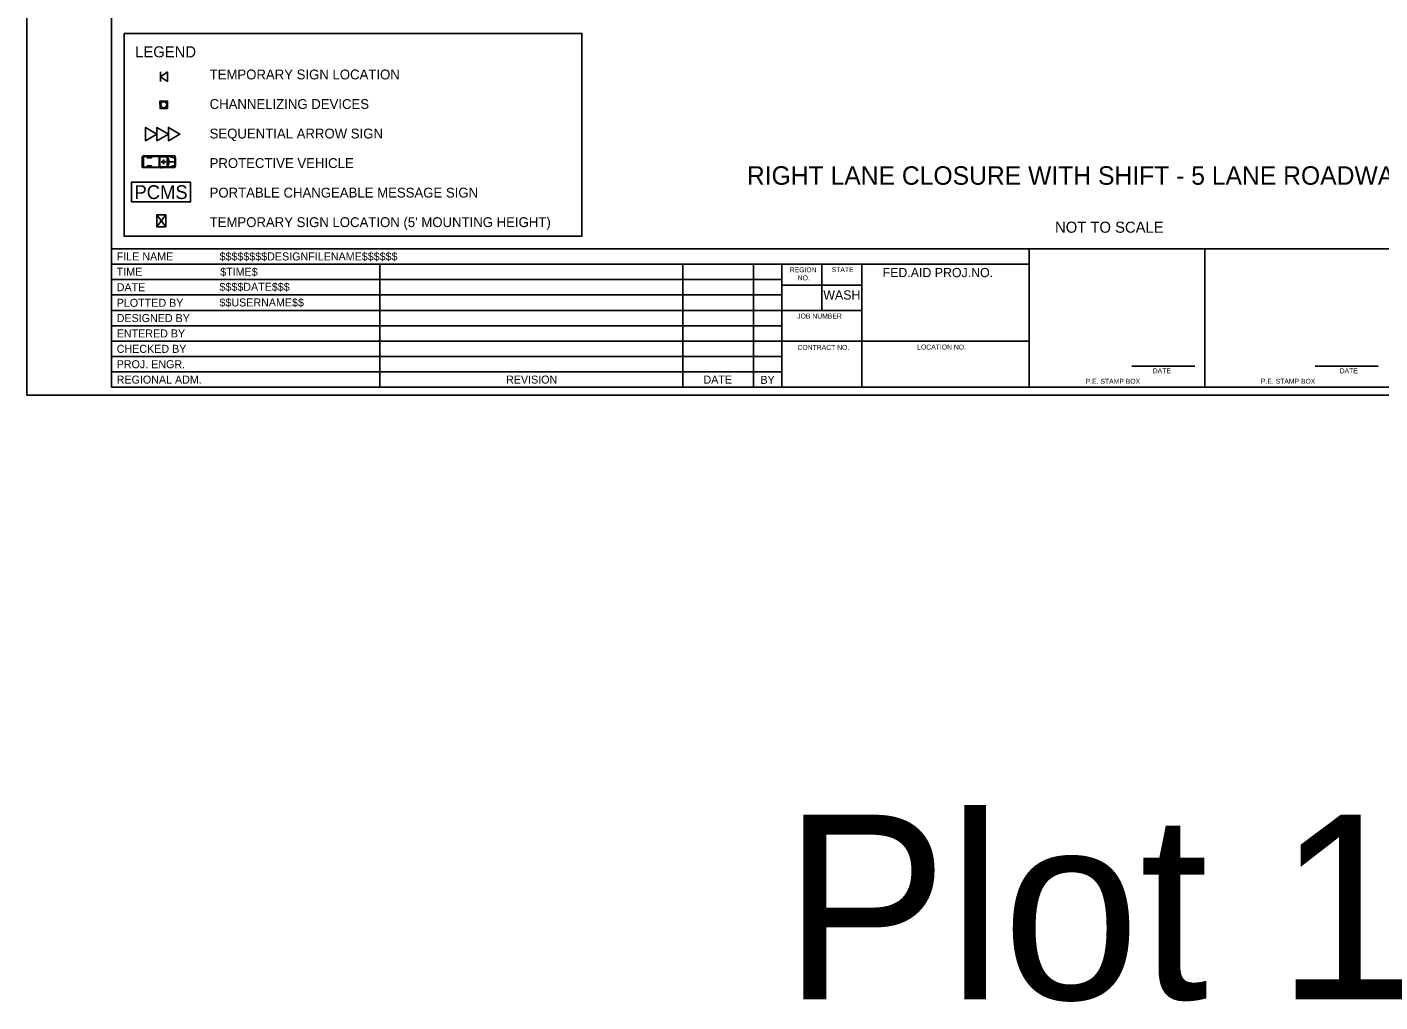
# Model space of a CAD drawing. Extents: x 99988 to 100172, y 99995 to 100047.
# Drawn here: x 99999.31 to 100010.31, y 99995.01 to 100002.93 of the extents above; entities that cross this region are included whole.
import ezdxf

# ---------------------------------------------------------------- set-up
doc = ezdxf.new("R2010")
doc.units = 0
for name, color, linetype in [('Default', 7, 'Continuous'), ('SH_DE_DetailBody1Text', 7, 'Continuous'), ('SH_DE_DetailHeading1Text', 7, 'Continuous'), ('SH_DE_DetailHeading2Text', 7, 'Continuous'), ('SH_DE_DetailHeading3Text', 7, 'Continuous'), ('SH_GI_PlotLimits', 7, 'Continuous'), ('SH_GI_SheetBorder', 7, 'Continuous'), ('SH_GI_SheetLocationText', 7, 'Continuous'), ('SH_GI_SheetTextInCells', 7, 'Continuous'), ('SH_GI_TitleBlockText', 7, 'Continuous'), ('SH_TI_BufferDataNote', 7, 'Continuous'), ('TR_WZ_PortableChangeMessageSign', 7, 'Continuous'), ('TR_WZ_SequentialArrowTypeC', 7, 'Continuous'), ('TR_WZ_TrafficSafetyCone', 7, 'Continuous'), ('TR_WZ_TruckBuffer', 7, 'Continuous')]:
    doc.layers.add(name, color=color, linetype=linetype)

msp = doc.modelspace()

# ---------------------------------------------------------------- linework, layer by layer
at = {"layer": 'Default'}
for p, q in [((100000.455, 100002.564), (100000.398, 100002.524)), ((100000.398, 100002.484), (100000.398, 100002.564)), ((100000.455, 100002.484), (100000.455, 100002.564)), ((100000.455, 100002.484), (100000.398, 100002.524)), ((100000.439, 100001.401), (100000.366, 100001.303)), ((100000.366, 100001.401), (100000.439, 100001.303)), ((100000.403, 100001.352), (100000.403, 100001.352)), ((100000.403, 100001.352), (100000.403, 100001.352))]:
    msp.add_line(p, q, dxfattribs=at)
msp.add_lwpolyline([(100000.439, 100001.401), (100000.366, 100001.401), (100000.366, 100001.303), (100000.439, 100001.303)], close=True, dxfattribs=at)
at = {"layer": 'SH_GI_PlotLimits'}
msp.add_lwpolyline([(99999.312, 99999.937), (100015.812, 99999.937), (100015.812, 100010.437), (99999.312, 100010.437)], close=True, dxfattribs=at)
at = {"layer": 'SH_GI_SheetBorder'}
for p, q in [((100000, 100010.375), (100000, 100000)), ((100000, 100001.126), (100015.75, 100001.126)), ((100007.457, 100000), (100007.457, 100001.126)), ((100008.883, 100000), (100008.883, 100001.126)), ((100000, 100001.001), (100007.457, 100001.001)), ((100002.179, 100001.001), (100002.179, 100000)), ((100004.641, 100001.001), (100004.641, 100000)), ((100005.216, 100001.001), (100005.216, 100000)), ((100005.445, 100001.001), (100005.445, 100000)), ((100005.772, 100000.625), (100005.772, 100001.001)), ((100006.096, 100000), (100006.096, 100001.001)), ((100000, 100000.876), (100002.182, 100000.876)), ((100002.182, 100000.876), (100005.447, 100000.876)), ((100006.096, 100000.831), (100005.447, 100000.831)), ((100000, 100000.751), (100002.182, 100000.751)), ((100002.182, 100000.751), (100005.447, 100000.751)), ((100000, 100000.625), (100005.447, 100000.625)), ((100006.096, 100000.625), (100005.447, 100000.625)), ((100000, 100000.5), (100005.447, 100000.5)), ((100000, 100000.375), (100005.447, 100000.375)), ((100007.457, 100000.375), (100005.447, 100000.375)), ((100000, 100000.25), (100005.447, 100000.25)), ((100000, 100000.125), (100005.447, 100000.125)), ((100008.29, 100000.173), (100008.802, 100000.173)), ((100009.78, 100000.173), (100010.291, 100000.173)), ((100000, 100000), (100015.75, 100000))]:
    msp.add_line(p, q, dxfattribs=at)
at = {"layer": 'SH_TI_BufferDataNote'}
msp.add_lwpolyline([(100000.101, 100002.876), (100003.821, 100002.876), (100003.821, 100001.227), (100000.101, 100001.227)], close=True, dxfattribs=at)
at = {"layer": 'TR_WZ_PortableChangeMessageSign'}
msp.add_lwpolyline([(100000.161, 100001.506), (100000.641, 100001.506), (100000.641, 100001.666), (100000.161, 100001.666)], close=True, dxfattribs=at)
at = {"layer": 'TR_WZ_SequentialArrowTypeC'}
msp.add_lwpolyline([(100000.275, 100002.004), (100000.275, 100002.112), (100000.368, 100002.058), (100000.368, 100002.112), (100000.461, 100002.058), (100000.461, 100002.112), (100000.554, 100002.058), (100000.461, 100002.004), (100000.461, 100002.058), (100000.368, 100002.004), (100000.368, 100002.058)], close=True, dxfattribs=at)
at = {"layer": 'TR_WZ_TrafficSafetyCone'}
msp.add_lwpolyline([(100000.453, 100002.327), (100000.392, 100002.326), (100000.393, 100002.265), (100000.454, 100002.266)], close=True, dxfattribs=at)
msp.add_circle((100000.423, 100002.296), 0.0244, dxfattribs=at)
at = {"layer": 'TR_WZ_TruckBuffer'}
for p, q in [((100000.249, 100001.876), (100000.249, 100001.789)), ((100000.249, 100001.839), (100000.254, 100001.837)), ((100000.249, 100001.826), (100000.254, 100001.828)), ((100000.25, 100001.832), (100000.253, 100001.832)), ((100000.252, 100001.879), (100000.254, 100001.879)), ((100000.252, 100001.834), (100000.252, 100001.831)), ((100000.252, 100001.786), (100000.254, 100001.786)), ((100000.254, 100001.879), (100000.254, 100001.786)), ((100000.255, 100001.88), (100000.389, 100001.88)), ((100000.255, 100001.88), (100000.255, 100001.785)), ((100000.255, 100001.785), (100000.389, 100001.785)), ((100000.259, 100001.876), (100000.259, 100001.789)), ((100000.259, 100001.876), (100000.385, 100001.876)), ((100000.259, 100001.789), (100000.385, 100001.789)), ((100000.289, 100001.876), (100000.289, 100001.865)), ((100000.289, 100001.865), (100000.325, 100001.865)), ((100000.289, 100001.789), (100000.289, 100001.8)), ((100000.289, 100001.8), (100000.325, 100001.8)), ((100000.296, 100001.876), (100000.296, 100001.865)), ((100000.296, 100001.789), (100000.296, 100001.8)), ((100000.318, 100001.876), (100000.318, 100001.865)), ((100000.318, 100001.789), (100000.318, 100001.8)), ((100000.325, 100001.876), (100000.325, 100001.865)), ((100000.325, 100001.789), (100000.325, 100001.8)), ((100000.385, 100001.876), (100000.385, 100001.789)), ((100000.389, 100001.88), (100000.389, 100001.785)), ((100000.391, 100001.88), (100000.391, 100001.785)), ((100000.514, 100001.88), (100000.391, 100001.88)), ((100000.451, 100001.873), (100000.391, 100001.873)), ((100000.451, 100001.792), (100000.391, 100001.792)), ((100000.514, 100001.785), (100000.391, 100001.785)), ((100000.407, 100001.881), (100000.4, 100001.881)), ((100000.407, 100001.783), (100000.4, 100001.783)), ((100000.401, 100001.832), (100000.411, 100001.832)), ((100000.412, 100001.832), (100000.412, 100001.832)), ((100000.421, 100001.814), (100000.421, 100001.821)), ((100000.422, 100001.851), (100000.422, 100001.844)), ((100000.441, 100001.833), (100000.433, 100001.832)), ((100000.451, 100001.88), (100000.443, 100001.873)), ((100000.445, 100001.792), (100000.451, 100001.785)), ((100000.451, 100001.88), (100000.451, 100001.785)), ((100000.452, 100001.88), (100000.452, 100001.785)), ((100000.514, 100001.863), (100000.452, 100001.88)), ((100000.514, 100001.802), (100000.452, 100001.785)), ((100000.514, 100001.832), (100000.464, 100001.832)), ((100000.514, 100001.88), (100000.514, 100001.785)), ((100000.514, 100001.88), (100000.52, 100001.861)), ((100000.514, 100001.785), (100000.52, 100001.804)), ((100000.52, 100001.861), (100000.52, 100001.804))]:
    msp.add_line(p, q, dxfattribs=at)
for centre, radius in [((100000.252, 100001.832), 0.00134), ((100000.422, 100001.832), 0.00918)]:
    msp.add_circle(centre, radius, dxfattribs=at)
for centre, radius, start, end in [((100000.252, 100001.876), 0.00291, 90, 180), ((100000.252, 100001.789), 0.00291, 180, 270), ((100000.364, 100001.832), 0.1, 331.5505, 28.46)]:
    msp.add_arc(centre, radius, start, end, dxfattribs=at)

# ---------------------------------------------------------------- texts
at = {"layer": 'SH_DE_DetailBody1Text'}
for s, p in [('TEMPORARY SIGN LOCATION', (100000.796, 100002.502)), ('CHANNELIZING DEVICES', (100000.796, 100002.262)), ('SEQUENTIAL ARROW SIGN', (100000.796, 100002.022)), ('PROTECTIVE VEHICLE', (100000.796, 100001.782)), ('PORTABLE CHANGEABLE MESSAGE SIGN', (100000.796, 100001.542)), ("TEMPORARY SIGN LOCATION (5' MOUNTING HEIGHT)", (100000.796, 100001.302))]:
    msp.add_text(s, height=0.08, dxfattribs=at).set_placement(p)
at = {"layer": 'SH_DE_DetailHeading1Text'}
msp.add_text('RIGHT LANE CLOSURE WITH SHIFT - 5 LANE ROADWAY', height=0.15, dxfattribs=at).set_placement((100005.162, 100001.646))
at = {"layer": 'SH_DE_DetailHeading2Text'}
msp.add_text('LEGEND', height=0.09, dxfattribs=at).set_placement((100000.191, 100002.681))
at = {"layer": 'SH_DE_DetailHeading3Text'}
msp.add_text('NOT TO SCALE', height=0.09, dxfattribs=at).set_placement((100007.666, 100001.256))
at = {"layer": 'SH_GI_SheetLocationText'}
msp.add_text('Plot 1', height=1.5, dxfattribs=at).set_placement((100005.455, 99995.027))
at = {"layer": 'SH_GI_SheetTextInCells'}
for s, height, p in [('FILE NAME', 0.0651, (100000.041, 100001.031)), ('TIME', 0.0651, (100000.041, 100000.906)), ('REGION', 0.04, (100005.51, 100000.935)), ('NO.', 0.04, (100005.575, 100000.869)), ('STATE', 0.04, (100005.851, 100000.936)), ('FED.AID PROJ.NO.', 0.07506, (100006.265, 100000.895)), ('DATE', 0.0651, (100000.041, 100000.781)), ('WASH', 0.0751, (100005.783, 100000.713)), ('PLOTTED BY', 0.0651, (100000.041, 100000.654)), ('DESIGNED BY', 0.06505, (100000.041, 100000.53)), ('JOB NUMBER', 0.04, (100005.571, 100000.559)), ('ENTERED BY', 0.0651, (100000.041, 100000.405)), ('CHECKED BY', 0.0651, (100000.041, 100000.28)), ('CONTRACT NO.', 0.04003, (100005.573, 100000.304)), ('LOCATION NO.', 0.04003, (100006.546, 100000.307)), ('PROJ. ENGR.', 0.06505, (100000.041, 100000.155)), ('DATE', 0.04, (100008.46, 100000.114)), ('DATE', 0.04, (100009.979, 100000.114)), ('REGIONAL ADM.', 0.06505, (100000.041, 100000.03)), ('REVISION', 0.0651, (100003.205, 100000.03)), ('DATE', 0.0651, (100004.809, 100000.03)), ('BY', 0.0651, (100005.272, 100000.028)), ('P.E. STAMP BOX', 0.04003, (100007.915, 100000.029)), ('P.E. STAMP BOX', 0.04003, (100009.339, 100000.029))]:
    msp.add_text(s, height=height, dxfattribs=at).set_placement(p)
at = {"layer": 'SH_GI_TitleBlockText'}
for s, height, p in [('$$$$$$$$DESIGNFILENAME$$$$$$', 0.06505, (100000.877, 100001.031)), ('$TIME$', 0.0651, (100000.882, 100000.906)), ('$$$$DATE$$$', 0.06505, (100000.876, 100000.784)), ('$$USERNAME$$', 0.06505, (100000.876, 100000.657))]:
    msp.add_text(s, height=height, dxfattribs=at).set_placement(p)
at = {"layer": 'TR_WZ_PortableChangeMessageSign'}
msp.add_text('PCMS', height=0.112, rotation=360, dxfattribs=at).set_placement((100000.185, 100001.53))

doc.saveas('drawing.dxf')
